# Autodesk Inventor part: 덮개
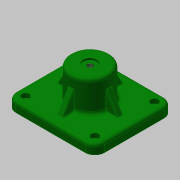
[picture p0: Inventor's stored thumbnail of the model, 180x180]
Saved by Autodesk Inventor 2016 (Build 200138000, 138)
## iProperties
Created: 2017-08
Part Number: 덮개
Material: 알루미늄 6061
Document SubType Name: Modeling
Designer: mduedu
Density: 1 g/cm^3
Appearance: 진녹색
Author: mduedu
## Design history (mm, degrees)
sketch "스케치1"
  geometry: L1 (46, -41)-(-46, -41); L2 (-46, -41)-(-46, 41); L3 (-46, 41)-(46, 41); L4 (46, 41)-(46, -41); 1 further point
  constraints: 8 end point, 2 parallel, 1 horizontal, 1 perpendicular
  dimensions: "d0" = 92 distance of L2.end L3.end; "d2" = 82 distance of L1.end L2.end; "d3" = 41 distance from line of L3 point (0, 0) (= 0.5 x d2); "d4" = 46 distance from line of point (0, 0) L4 (= 0.5 x d0)
extrude "돌출1" new body sketch "스케치1" distance "d5" = 10; taper "d6" = 0 deg
sketch "스케치2"
  geometry: C1 r 20 at (0, 0); 1 further point
  constraints: 1 centre point, 1 coincident
  dimensions: "d55" = 40 diameter of C1
extrude "돌출2" join sketch "스케치2" distance "d9" = 32; taper "d10" = 0 deg
sketch "스케치3"
  geometry: L1 (-26, -26)-(26, -26); L2 (26, -26)-(26, 26); L3 (26, 26)-(-26, 26); L4 (-26, 26)-(-26, -26); L5 (-26, -26)-(26, 26); L6 (26, -26)-(-26, 26); 1 further point
  constraints: 12 end point, 2 midpoint, 2 parallel, 2 perpendicular, 1 horizontal
  dimensions: "d11" = 52 distance of L3.end L2.end
extrude "돌출3" join sketch "스케치3" distance "d12" = 6; taper "d13" = 0 deg
sketch "스케치4"
  geometry: L1 (-17, -17)-(17, -17); L2 (17, -17)-(17, 17); L3 (17, 17)-(-17, 17); L4 (-17, 17)-(-17, -17); L5 (-17, -17)-(17, 17); L6 (17, -17)-(-17, 17); 1 further point
  constraints: 12 end point, 2 midpoint, 2 parallel, 2 perpendicular, 1 horizontal
  dimensions: "d14" = 34 distance of L2.end L3.end
extrude "돌출4" cut sketch "스케치4" distance "d16" = 5; taper "d17" = 0 deg
sketch "스케치5"
  geometry: C1 r 9 at (0, 0); 1 further point
  constraints: 1 centre point, 1 coincident
  dimensions: "d18" = 18 diameter of C1
extrude "돌출5" cut sketch "스케치5" distance "d19" = 34; taper "d20" = 0 deg
sketch "스케치6"
  geometry: 2 further points
  constraints: 1 coincident
hole "구멍1" sketch "스케치6" at (0, 0) diameter "d21" = 5.917; stored, may be unused: countersink angle "d25" = 90 deg, drill point angle "d27" = 118 deg; dims "d22" = 6, "d23" = 14, "d24" = 2, "d26" = 8
fillet "모깎기1" dims "d36" = 10
fillet "모깎기3" dims "d38" = 3
fillet "모깎기4" dims "d39" = 3
fillet "모깎기5" dims "d40" = 3
chamfer "모따기1" distance "d41" = 1; stored, may be unused: second distance "d42" = 2, angle "d43" = 45 deg
fillet "모깎기6" dims "d44" = 3
fillet "모깎기7" dims "d45" = 3
fillet "모깎기8" dims "d46" = 3
sketch "스케치8"
  geometry: A1 r 10 centre (-36, -31) between (-46, -31) and (-36, -41) reference; A2 r 10 centre (-36, 31) between (-36, 41) and (-46, 31) reference; A3 r 10 centre (36, 31) between (46, 31) and (36, 41) reference; A4 r 10 centre (36, -31) between (36, -41) and (46, -31) reference; 5 further points
  constraints: 4 coincident
sketch "스케치9"
  geometry: 4 further points
  constraints: 4 other
hole "구멍3" sketch "스케치9" at (-36, -31), (-36, 31), (36, 31), (36, -31) diameter "d48" = 4.5; stored, may be unused: countersink angle "d52" = 90 deg, drill point angle "d54" = 0 deg; dims "d49" = 6, "d50" = 8, "d51" = 4.6, "d53" = 8
sketch "스케치10"
  geometry: L1 (-7, 40)-(-2.958, 40) reference; L2 (-2.958, 40)-(-2.958, 33) reference; L3 (-2.958, 33)-(-6, 33) reference; L4 (-9, 30)-(-9, -1) reference; L5 (-9, -1)-(-14, -1) reference; L6 (-17, -4)-(-17, -6) reference; L7 (-17, -6)-(-25, -6) reference; L8 (-25, -6)-(-26, -5) reference; L9 (-26, -5)-(-26, 0) reference; L10 (-26, 0)-(-46, 0) reference; L11 (-46, 0)-(-46, 7) reference; L12 (-43, 10)-(-23, 10) reference; L13 (-20, 13)-(-20, 39) reference; L14 (-17, 42)-(-7, 42) reference; L15 (-7, 42)-(-7, 40) reference; L16 (2.958, 40)-(7, 40) reference; L17 (7, 40)-(7, 42) reference; L18 (7, 42)-(17, 42) reference; L19 (20, 39)-(20, 13) reference; L20 (23, 10)-(43, 10) reference; L21 (46, 7)-(46, 0) reference; L22 (46, 0)-(26, 0) reference; L23 (26, 0)-(26, -5) reference; L24 (26, -5)-(25, -6) reference; L25 (25, -6)-(17, -6) reference; L26 (17, -6)-(17, -4) reference; L27 (14, -1)-(9, -1) reference; L28 (9, -1)-(9, 30) reference; L29 (6, 33)-(2.958, 33) reference; L30 (2.958, 33)-(2.958, 40) reference; L31 (31.547, 10)-(20, 30); A1 r 3 centre (-6, 30) between (-6, 33) and (-9, 30) reference; A2 r 3 centre (-14, -4) between (-14, -1) and (-17, -4) reference; A3 r 3 centre (-43, 7) between (-43, 10) and (-46, 7) reference; A4 r 3 centre (-23, 13) between (-23, 10) and (-20, 13) reference; A5 r 3 centre (-17, 39) between (-17, 42) and (-20, 39) reference; A6 r 3 centre (17, 39) between (20, 39) and (17, 42) reference; A7 r 3 centre (23, 13) between (20, 13) and (23, 10) reference; A8 r 3 centre (43, 7) between (46, 7) and (43, 10) reference; A9 r 3 centre (14, -4) between (17, -4) and (14, -1) reference; A10 r 3 centre (6, 30) between (9, 30) and (6, 33) reference; 1 further point
  constraints: 2 end point, 2 point on line
  dimensions: "d56" = 20 distance from line of L31.end L20; "d57" = 120 deg angle of L31 L20
feature "리브1" sketch "스케치10" dims "d58" = 1, "d59" = 6, "d60" = 0, "d61" = 0, "d62" = 1, "d63" = 1
fillet "모깎기9" dims "d64" = 1
fillet "모깎기10" dims "d65" = 1
node "솔리드1"
pattern_circular "원형 패턴1" dims "d67" = 360 deg
node "절단 모서리 투영1"
